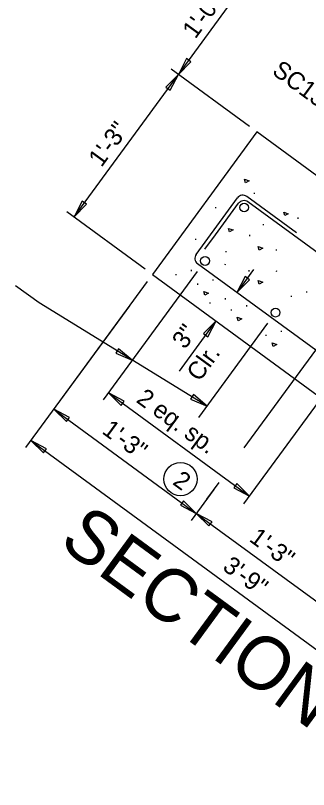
# Model space of a CAD drawing. Extents: x 1970654 to 1970899, y 796145 to 796378.
# Drawn here: x 1970793.83 to 1970802.12, y 796198.88 to 796220.79 of the extents above; entities that cross this region are included whole.
import ezdxf

# ---------------------------------------------------------------- set-up
doc = ezdxf.new("R2010")
doc.units = 0
for name, color, linetype in [('BR_AUTO DIMENSION', 7, 'Continuous'), ('BR_CONCRETE', 7, 'Continuous'), ('BR_DETAILS', 7, 'Continuous'), ('BR_REBAR', 7, 'Continuous'), ('BR_TEXT', 7, 'Continuous')]:
    doc.layers.add(name, color=color, linetype=linetype)

msp = doc.modelspace()

# ---------------------------------------------------------------- linework, layer by layer
at = {"layer": 'BR_AUTO DIMENSION'}
for p, q in [((1970798.436, 796219.117), (1970800.799, 796222.345)), ((1970795.483, 796215.083), (1970798.436, 796219.117)), ((1970800.452, 796217.641), (1970798.235, 796219.265)), ((1970800.452, 796217.641), (1970798.235, 796219.265)), ((1970797.498, 796213.607), (1970795.281, 796215.231)), ((1970800.301, 796208.548), (1970804.468, 796214.239)), ((1970798.973, 796213.541), (1970796.311, 796209.905)), ((1970800.565, 796213.592), (1970800.093, 796212.947)), ((1970797.552, 796213.258), (1970794.762, 796209.446)), ((1970794.492, 796212.651), (1970793.826, 796213.139)), ((1970797.051, 796212.572), (1970794.112, 796208.559)), ((1970799.25, 796209.73), (1970794.492, 796212.651)), ((1970798.465, 796210.723), (1970799.502, 796212.14)), ((1970799.014, 796209.408), (1970800.97, 796212.079)), ((1970800.294, 796206.966), (1970802.967, 796210.617)), ((1970796.459, 796210.106), (1970800.452, 796207.183)), ((1970794.91, 796209.648), (1970798.944, 796206.694)), ((1970794.26, 796208.761), (1970806.363, 796199.9)), ((1970799.238, 796207.095), (1970799.588, 796207.573)), ((1970799.44, 796207.372), (1970798.796, 796206.493)), ((1970798.944, 796206.694), (1970802.978, 796203.741))]:
    msp.add_line(p, q, dxfattribs=at)
for points in [[(1970798.671, 796219.565), (1970798.436, 796219.117), (1970798.792, 796219.476)], [(1970798.201, 796218.669), (1970798.436, 796219.117), (1970798.08, 796218.758)], [(1970795.717, 796215.531), (1970795.483, 796215.083), (1970795.839, 796215.442)], [(1970800.328, 796213.395), (1970800.093, 796212.947), (1970800.449, 796213.306)], [(1970799.267, 796211.692), (1970799.502, 796212.14), (1970799.146, 796211.781)], [(1970796.668, 796211.227), (1970797.133, 796211.03), (1970796.746, 796211.355)], [(1970796.907, 796209.872), (1970796.459, 796210.106), (1970796.818, 796209.751)], [(1970798.784, 796209.928), (1970799.249, 796209.731), (1970798.862, 796210.056)], [(1970795.358, 796209.413), (1970794.91, 796209.648), (1970795.269, 796209.292)], [(1970794.708, 796208.526), (1970794.26, 796208.761), (1970794.619, 796208.405)], [(1970800.005, 796207.418), (1970800.452, 796207.183), (1970800.093, 796207.539)], [(1970798.496, 796206.929), (1970798.944, 796206.694), (1970798.585, 796207.05)], [(1970799.392, 796206.459), (1970798.944, 796206.694), (1970799.303, 796206.338)]]:
    msp.add_lwpolyline(points, close=True, dxfattribs=at)
msp.add_circle((1970798.497, 796207.665), 0.472, dxfattribs=at)
at = {"layer": 'BR_CONCRETE'}
for p, q in [((1970800.654, 796217.494), (1970797.7, 796213.459)), ((1970804.688, 796214.54), (1970800.654, 796217.494)), ((1970797.7, 796213.459), (1970809.803, 796204.598))]:
    msp.add_line(p, q, dxfattribs=at)
at = {"layer": 'BR_DETAILS'}
for p, q in [((1970800.591, 796215.735), (1970800.592, 796215.765)), ((1970799.496, 796215.332), (1970799.497, 796215.362)), ((1970801.83, 796215.034), (1970801.832, 796215.064)), ((1970800.848, 796214.853), (1970800.85, 796214.883)), ((1970800.456, 796214.544), (1970800.458, 796214.574)), ((1970798.929, 796214.438), (1970798.93, 796214.468)), ((1970799.792, 796214.09), (1970799.793, 796214.12)), ((1970801.212, 796214.136), (1970801.213, 796214.166)), ((1970799.765, 796213.73), (1970799.767, 796213.76)), ((1970798.376, 796213.438), (1970798.377, 796213.468)), ((1970798.81, 796213.554), (1970798.812, 796213.584)), ((1970800.437, 796213.543), (1970800.439, 796213.573)), ((1970801.217, 796213.542), (1970801.219, 796213.572)), ((1970798.99, 796213.167), (1970798.992, 796213.197)), ((1970799.425, 796213.283), (1970799.426, 796213.313)), ((1970802.069, 796212.942), (1970802.07, 796212.972)), ((1970799.77, 796212.752), (1970799.771, 796212.782)), ((1970801.634, 796212.826), (1970801.636, 796212.856)), ((1970799.335, 796212.637), (1970799.337, 796212.667)), ((1970800.371, 796212.554), (1970800.372, 796212.584)), ((1970799.936, 796212.438), (1970799.938, 796212.468)), ((1970801.356, 796211.832), (1970801.358, 796211.862)), ((1970800.922, 796211.717), (1970800.923, 796211.747))]:
    msp.add_line(p, q, dxfattribs=at)
for points in [[(1970800.44, 796216.104), (1970800.338, 796216.05), (1970800.308, 796216.149), (1970800.44, 796216.104)], [(1970801.549, 796215.175), (1970801.447, 796215.12), (1970801.417, 796215.22), (1970801.549, 796215.175)], [(1970799.986, 796214.715), (1970799.884, 796214.66), (1970799.854, 796214.76), (1970799.986, 796214.715)], [(1970800.825, 796214.198), (1970800.723, 796214.144), (1970800.692, 796214.244), (1970800.825, 796214.198)], [(1970800.83, 796213.237), (1970800.728, 796213.182), (1970800.698, 796213.282), (1970800.83, 796213.237)], [(1970799.288, 796212.927), (1970799.186, 796212.873), (1970799.156, 796212.972), (1970799.288, 796212.927)], [(1970800.234, 796212.198), (1970800.133, 796212.144), (1970800.102, 796212.243), (1970800.234, 796212.198)], [(1970801.22, 796211.477), (1970801.118, 796211.422), (1970801.088, 796211.522), (1970801.22, 796211.477)]]:
    msp.add_lwpolyline(points, dxfattribs=at)
at = {"layer": 'BR_REBAR'}
for p, q in [((1970798.94, 796214.023), (1970800.109, 796215.62)), ((1970801.78, 796214.63), (1970800.371, 796215.661)), ((1970799.486, 796214.575), (1970800.14, 796215.469)), ((1970811.034, 796207.725), (1970800.402, 796215.509)), ((1970799.19, 796214.171), (1970799.486, 796214.575)), ((1970809.705, 796205.909), (1970798.98, 796213.761))]:
    msp.add_line(p, q, dxfattribs=at)
for centre in [(1970800.299, 796215.352), (1970799.192, 796213.839), (1970801.188, 796212.377)]:
    msp.add_circle(centre, 0.125, dxfattribs=at)
for centre, radius, start, end in [((1970800.26, 796215.51), 0.188, 53.7906, 143.7906), ((1970800.291, 796215.358), 0.188, 53.7906, 143.7906), ((1970799.091, 796213.913), 0.187, 143.7906, 233.7906)]:
    msp.add_arc(centre, radius, start, end, dxfattribs=at)

# ---------------------------------------------------------------- texts
at = {"layer": 'BR_AUTO DIMENSION'}
for s, rotation, p in [('1\'-0"', 53.7906, (1970798.917, 796220.1)), ('1\'-3"', 53.7906, (1970796.259, 796216.469)), ('3"', 53.7906, (1970798.623, 796211.317)), ('2 eq. sp.', 323.7906, (1970797.216, 796209.862)), ('1\'-3"', 323.7906, (1970796.246, 796208.979)), ('1\'-3"', 323.7906, (1970800.415, 796205.927)), ('3\'-9"', 323.7906, (1970799.659, 796205.118))]:
    msp.add_text(s, height=0.5, rotation=rotation, dxfattribs=at).set_placement(p)
at = {"layer": 'BR_TEXT'}
for s, height, rotation, p in [('SC1370G', 0.4999, 323.7906, (1970801.058, 796219.149)), ('Clr.', 0.5, 53.7906, (1970799.034, 796210.399)), ('2', 0.5, 323.7906, (1970798.247, 796207.537)), ('SECTION F-F', 1.5, 323.7906, (1970795.015, 796205.803))]:
    msp.add_text(s, height=height, rotation=rotation, dxfattribs=at).set_placement(p)

doc.saveas('drawing.dxf')
